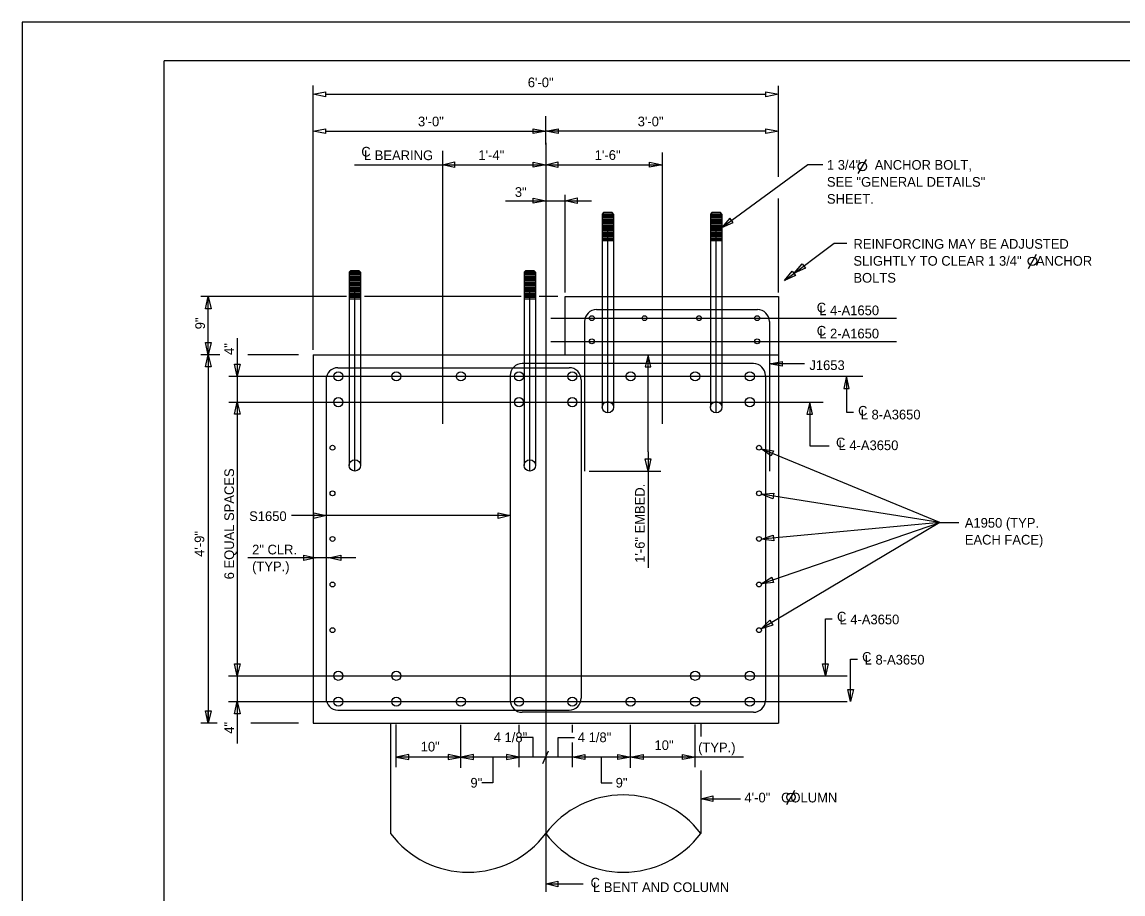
# Model space of a CAD drawing. Extents: x -133.1 to -97, y -1.7 to 20.3.
# Drawn here: x -133.14 to -118.94, y 9.06 to 20.31 of the extents above; entities that cross this region are included whole.
import ezdxf

# ---------------------------------------------------------------- set-up
doc = ezdxf.new("R2010")
doc.units = 0
for name, color, linetype in [('BR_AUTO DIMENSION', 7, 'Continuous'), ('BR_BORDER LINES', 7, 'Continuous'), ('BR_CENTER LINES', 7, 'Continuous'), ('BR_CONCRETE', 7, 'Continuous'), ('BR_REBAR', 7, 'Continuous'), ('BR_STRUCTURAL STEEL', 7, 'Continuous'), ('BR_TEXT', 7, 'Continuous'), ('Level 31', 7, 'Continuous')]:
    doc.layers.add(name, color=color, linetype=linetype)

msp = doc.modelspace()

# ---------------------------------------------------------------- linework, layer by layer
at = {"layer": 'BR_AUTO DIMENSION'}
for p, q in [((-129.388, 16.08), (-129.388, 19.492)), ((-123.388, 18.314), (-123.388, 19.485)), ((-129.221, 19.378), (-123.555, 19.378)), ((-126.388, 18.729), (-126.388, 19.097)), ((-129.221, 18.902), (-126.388, 18.902)), ((-123.555, 18.902), (-126.388, 18.902)), ((-128.854, 18.469), (-124.888, 18.469)), ((-126.388, 18.083), (-126.388, 17.91)), ((-126.138, 16.822), (-126.138, 18.081)), ((-123.388, 16.82), (-123.388, 18.032)), ((-126.908, 18.005), (-125.796, 18.005)), ((-128.958, 16.768), (-130.837, 16.768)), ((-130.74, 16.018), (-130.74, 16.768)), ((-126.703, 16.768), (-128.724, 16.768)), ((-126.231, 16.768), (-126.471, 16.768)), ((-130.365, 16.232), (-130.365, 11.006)), ((-130.589, 16.018), (-130.837, 16.018)), ((-130.74, 16.018), (-130.74, 11.268)), ((-129.575, 16.018), (-130.228, 16.018)), ((-125.068, 14.768), (-125.068, 16.018)), ((-123.051, 15.901), (-123.504, 15.901)), ((-122.983, 15.407), (-122.983, 14.845)), ((-125.068, 14.768), (-125.068, 13.272)), ((-121.307, 13.856), (-123.609, 14.806)), ((-122.983, 14.845), (-122.732, 14.845)), ((-125.826, 14.518), (-124.905, 14.518)), ((-121.307, 13.856), (-123.608, 14.222)), ((-126.846, 13.943), (-129.668, 13.943)), ((-121.307, 13.856), (-123.612, 12.483)), ((-121.307, 13.856), (-123.607, 13.64)), ((-128.835, 13.399), (-130.227, 13.399)), ((-130.626, 11.268), (-130.837, 11.268)), ((-129.575, 11.268), (-130.192, 11.268)), ((-128.315, 10.698), (-128.315, 11.249)), ((-127.482, 10.692), (-127.482, 11.244)), ((-126.732, 11.146), (-126.732, 11.246)), ((-126.044, 11.146), (-126.044, 11.246)), ((-125.294, 10.692), (-125.294, 11.244)), ((-124.461, 10.698), (-124.461, 11.249)), ((-126.55, 11.084), (-126.757, 11.084)), ((-126.55, 10.83), (-126.55, 11.084)), ((-126.226, 10.83), (-126.226, 11.084)), ((-126.226, 11.084), (-126.019, 11.084)), ((-126.732, 10.698), (-126.732, 11.016)), ((-126.044, 10.698), (-126.044, 11.016)), ((-123.839, 10.83), (-128.315, 10.83)), ((-127.068, 10.83), (-127.068, 10.498)), ((-126.425, 10.747), (-126.351, 10.912)), ((-125.675, 10.83), (-125.675, 10.498)), ((-127.068, 10.498), (-127.212, 10.498)), ((-125.675, 10.498), (-125.531, 10.498)), ((-124.388, 10.293), (-123.876, 10.293)), ((-126.388, 9.194), (-125.905, 9.194))]:
    msp.add_line(p, q, dxfattribs=at)
for points in [[(-129.226, 19.346), (-129.388, 19.378), (-129.226, 19.409)], [(-123.551, 19.409), (-123.388, 19.378), (-123.551, 19.346)], [(-129.226, 18.871), (-129.388, 18.902), (-129.226, 18.933)], [(-126.551, 18.933), (-126.388, 18.902), (-126.551, 18.871)], [(-126.226, 18.871), (-126.388, 18.902), (-126.226, 18.933)], [(-123.551, 18.933), (-123.388, 18.902), (-123.551, 18.871)], [(-127.565, 18.433), (-127.721, 18.469), (-127.565, 18.505)], [(-126.551, 18.501), (-126.388, 18.469), (-126.551, 18.438)], [(-126.232, 18.433), (-126.388, 18.469), (-126.232, 18.505)], [(-125.051, 18.501), (-124.888, 18.469), (-125.051, 18.438)], [(-126.551, 18.036), (-126.388, 18.005), (-126.551, 17.974)], [(-125.982, 17.969), (-126.138, 18.005), (-125.982, 18.041)], [(-124.012, 17.78), (-124.117, 17.659), (-123.97, 17.722)], [(-123.04, 17.134), (-123.186, 17.069), (-123.083, 17.191)], [(-123.165, 17.04), (-123.311, 16.976), (-123.208, 17.098)], [(-130.776, 16.612), (-130.74, 16.768), (-130.704, 16.612)], [(-130.704, 16.174), (-130.74, 16.018), (-130.776, 16.174)], [(-130.776, 15.862), (-130.74, 16.018), (-130.704, 15.862)], [(-125.032, 15.862), (-125.068, 16.018), (-125.104, 15.862)], [(-123.341, 15.87), (-123.504, 15.901), (-123.341, 15.933)], [(-130.329, 15.896), (-130.365, 15.74), (-130.401, 15.896)], [(-122.473, 15.584), (-122.509, 15.74), (-122.545, 15.584)], [(-130.401, 15.251), (-130.365, 15.407), (-130.329, 15.251)], [(-122.947, 15.251), (-122.983, 15.407), (-123.019, 15.251)], [(-123.479, 14.714), (-123.609, 14.806), (-123.451, 14.78)], [(-125.032, 14.674), (-125.068, 14.518), (-125.104, 14.674)], [(-123.46, 14.161), (-123.608, 14.222), (-123.448, 14.233)], [(-129.377, 13.979), (-129.221, 13.943), (-129.377, 13.907)], [(-127.002, 13.979), (-126.846, 13.943), (-127.002, 13.907)], [(-123.448, 13.619), (-123.607, 13.64), (-123.455, 13.691)], [(-129.509, 13.435), (-129.353, 13.399), (-129.509, 13.363)], [(-129.03, 13.363), (-129.186, 13.399), (-129.03, 13.435)], [(-123.449, 13.082), (-123.609, 13.065), (-123.473, 13.15)], [(-123.459, 12.532), (-123.612, 12.483), (-123.496, 12.594)], [(-130.329, 12.034), (-130.365, 11.878), (-130.401, 12.034)], [(-122.745, 12.034), (-122.781, 11.878), (-122.817, 12.034)], [(-122.421, 11.701), (-122.457, 11.545), (-122.493, 11.701)], [(-130.401, 11.389), (-130.365, 11.545), (-130.329, 11.389)], [(-130.704, 11.424), (-130.74, 11.268), (-130.776, 11.424)], [(-128.153, 10.861), (-128.315, 10.83), (-128.153, 10.799)], [(-127.644, 10.799), (-127.482, 10.83), (-127.644, 10.861)], [(-127.319, 10.861), (-127.482, 10.83), (-127.319, 10.799)], [(-126.894, 10.799), (-126.732, 10.83), (-126.894, 10.861)], [(-125.882, 10.799), (-126.044, 10.83), (-125.882, 10.861)], [(-125.457, 10.861), (-125.294, 10.83), (-125.457, 10.799)], [(-125.132, 10.799), (-125.294, 10.83), (-125.132, 10.861)], [(-124.623, 10.861), (-124.461, 10.83), (-124.623, 10.799)], [(-124.232, 10.257), (-124.388, 10.293), (-124.232, 10.329)], [(-126.232, 9.158), (-126.388, 9.194), (-126.232, 9.23)]]:
    msp.add_lwpolyline(points, close=True, dxfattribs=at)
for points in [[(-124.117, 17.659), (-123.008, 18.471), (-122.816, 18.471)], [(-123.311, 16.976), (-122.67, 17.455), (-122.505, 17.455)], [(-122.509, 15.74), (-122.509, 15.277), (-122.421, 15.277)], [(-123.609, 13.065), (-121.307, 13.856), (-121.06, 13.856)], [(-122.781, 11.878), (-122.781, 12.611), (-122.694, 12.611)], [(-122.457, 11.545), (-122.457, 12.091), (-122.369, 12.091)]]:
    msp.add_lwpolyline(points, dxfattribs=at)
at = {"layer": 'BR_BORDER LINES'}
for p in [(-97.642, 19.809), (-131.308, -1.191)]:
    msp.add_line(p, (-131.308, 19.809), dxfattribs=at)
at = {"layer": 'BR_CENTER LINES'}
for p, q in [((-126.388, 18.751), (-126.388, 9.09)), ((-127.721, 18.647), (-127.721, 15.128)), ((-124.888, 18.628), (-124.888, 15.128)), ((-125.586, 15.268), (-125.586, 17.64)), ((-124.19, 15.268), (-124.19, 17.64)), ((-128.849, 14.518), (-128.849, 16.89)), ((-126.593, 14.518), (-126.593, 16.89)), ((-126.323, 16.49), (-121.865, 16.49)), ((-126.323, 16.191), (-121.865, 16.191)), ((-130.476, 15.74), (-122.3, 15.74)), ((-130.476, 15.407), (-122.812, 15.407)), ((-130.477, 11.878), (-122.502, 11.878)), ((-130.477, 11.545), (-122.502, 11.545))]:
    msp.add_line(p, q, dxfattribs=at)
at = {"layer": 'BR_CONCRETE'}
for p, q in [((-126.138, 16.018), (-126.138, 16.768)), ((-126.138, 16.768), (-123.388, 16.768)), ((-123.388, 16.768), (-123.388, 11.268)), ((-129.388, 16.018), (-129.388, 11.268)), ((-129.388, 16.018), (-123.388, 16.018)), ((-129.388, 11.268), (-123.388, 11.268)), ((-128.388, 11.268), (-128.388, 9.843)), ((-124.388, 11.268), (-124.388, 11.095)), ((-124.388, 10.656), (-124.388, 9.843))]:
    msp.add_line(p, q, dxfattribs=at)
for centre, start, end in [((-125.388, 9.09), 37.0023, 142.9977), ((-127.388, 10.597), 217.0023, 322.9977), ((-125.388, 10.597), 217.0023, 322.9977)]:
    msp.add_arc(centre, 1.252, start, end, dxfattribs=at)
at = {"layer": 'BR_REBAR'}
for p, q in [((-125.732, 16.601), (-123.658, 16.601)), ((-125.886, 16.447), (-125.886, 14.518)), ((-123.504, 16.447), (-123.504, 14.518)), ((-123.709, 15.905), (-126.69, 15.905)), ((-129.067, 15.851), (-126.086, 15.851)), ((-129.221, 15.697), (-129.221, 11.588)), ((-126.846, 15.749), (-126.846, 11.563)), ((-125.93, 15.695), (-125.93, 11.591)), ((-123.555, 15.747), (-123.555, 11.561)), ((-129.067, 11.434), (-126.086, 11.434)), ((-123.709, 11.407), (-126.69, 11.407))]:
    msp.add_line(p, q, dxfattribs=at)
for centre, radius in [((-125.793, 16.49), 0.0313), ((-125.113, 16.49), 0.0313), ((-124.411, 16.49), 0.0313), ((-123.662, 16.49), 0.0313), ((-125.793, 16.191), 0.0313), ((-123.662, 16.191), 0.0313), ((-129.063, 15.74), 0.0588), ((-128.315, 15.74), 0.0588), ((-127.482, 15.74), 0.0588), ((-126.732, 15.74), 0.0588), ((-126.044, 15.74), 0.0588), ((-125.294, 15.74), 0.0588), ((-124.461, 15.74), 0.0588), ((-123.756, 15.74), 0.0588), ((-129.063, 15.407), 0.0588), ((-126.732, 15.407), 0.0588), ((-126.044, 15.407), 0.0588), ((-123.756, 15.407), 0.0588), ((-129.138, 14.819), 0.0313), ((-123.638, 14.819), 0.0313), ((-129.138, 14.231), 0.0313), ((-123.638, 14.231), 0.0313), ((-129.138, 13.643), 0.0313), ((-123.638, 13.643), 0.0313), ((-129.138, 13.055), 0.0313), ((-123.638, 13.055), 0.0313), ((-129.138, 12.467), 0.0313), ((-123.638, 12.467), 0.0313), ((-129.063, 11.878), 0.0588), ((-128.315, 11.878), 0.0588), ((-124.461, 11.878), 0.0588), ((-123.756, 11.878), 0.0588), ((-129.063, 11.545), 0.0588), ((-128.315, 11.545), 0.0588), ((-127.482, 11.545), 0.0588), ((-126.732, 11.545), 0.0588), ((-126.044, 11.545), 0.0588), ((-125.294, 11.545), 0.0588), ((-124.461, 11.545), 0.0588), ((-123.756, 11.545), 0.0588)]:
    msp.add_circle(centre, radius, dxfattribs=at)
for centre, start, end in [((-125.73, 16.445), 91.025, 178.975), ((-123.66, 16.445), 1.025, 88.975), ((-126.69, 15.749), 90, 180), ((-123.711, 15.749), 1.025, 88.975), ((-129.065, 15.695), 91.025, 178.975), ((-126.086, 15.695), 0, 90), ((-129.065, 11.591), 181.025, 268.975), ((-126.69, 11.563), 180, 270), ((-126.086, 11.591), 270, 0), ((-123.711, 11.563), 271.025, 358.975)]:
    msp.add_arc(centre, 0.156, start, end, dxfattribs=at)
at = {"layer": 'BR_STRUCTURAL STEEL'}
for p, q in [((-125.641, 17.851), (-125.659, 17.833)), ((-125.513, 17.833), (-125.659, 17.833)), ((-125.659, 17.833), (-125.659, 16.768)), ((-125.513, 17.815), (-125.659, 17.815)), ((-125.513, 17.797), (-125.659, 17.797)), ((-125.513, 17.778), (-125.659, 17.778)), ((-125.513, 17.76), (-125.659, 17.76)), ((-125.532, 17.851), (-125.641, 17.851)), ((-125.513, 17.833), (-125.532, 17.851)), ((-125.513, 17.833), (-125.513, 16.768)), ((-124.244, 17.851), (-124.263, 17.833)), ((-124.117, 17.833), (-124.263, 17.833)), ((-124.263, 17.833), (-124.263, 16.768)), ((-124.117, 17.815), (-124.263, 17.815)), ((-124.117, 17.797), (-124.263, 17.797)), ((-124.117, 17.778), (-124.263, 17.778)), ((-124.117, 17.76), (-124.263, 17.76)), ((-124.135, 17.851), (-124.244, 17.851)), ((-124.117, 17.833), (-124.135, 17.851)), ((-124.117, 17.833), (-124.117, 16.768)), ((-125.513, 17.742), (-125.659, 17.742)), ((-125.513, 17.724), (-125.659, 17.724)), ((-125.513, 17.705), (-125.659, 17.705)), ((-125.513, 17.687), (-125.659, 17.687)), ((-125.513, 17.669), (-125.659, 17.669)), ((-125.513, 17.651), (-125.659, 17.651)), ((-125.513, 17.632), (-125.659, 17.632)), ((-125.513, 17.614), (-125.659, 17.614)), ((-124.117, 17.742), (-124.263, 17.742)), ((-124.117, 17.724), (-124.263, 17.724)), ((-124.117, 17.705), (-124.263, 17.705)), ((-124.117, 17.687), (-124.263, 17.687)), ((-124.117, 17.669), (-124.263, 17.669)), ((-124.117, 17.651), (-124.263, 17.651)), ((-124.117, 17.632), (-124.263, 17.632)), ((-124.117, 17.614), (-124.263, 17.614)), ((-125.513, 17.596), (-125.659, 17.596)), ((-125.513, 17.578), (-125.659, 17.578)), ((-125.513, 17.56), (-125.659, 17.56)), ((-125.513, 17.541), (-125.659, 17.541)), ((-125.513, 17.523), (-125.659, 17.523)), ((-125.513, 17.505), (-125.659, 17.505)), ((-125.513, 17.487), (-125.659, 17.487)), ((-124.117, 17.596), (-124.263, 17.596)), ((-124.117, 17.578), (-124.263, 17.578)), ((-124.117, 17.56), (-124.263, 17.56)), ((-124.117, 17.541), (-124.263, 17.541)), ((-124.117, 17.523), (-124.263, 17.523)), ((-124.117, 17.505), (-124.263, 17.505)), ((-124.117, 17.487), (-124.263, 17.487)), ((-128.904, 17.101), (-128.922, 17.083)), ((-128.776, 17.083), (-128.922, 17.083)), ((-128.922, 17.083), (-128.922, 16.018)), ((-128.776, 17.065), (-128.922, 17.065)), ((-128.776, 17.047), (-128.922, 17.047)), ((-128.795, 17.101), (-128.904, 17.101)), ((-128.776, 17.083), (-128.795, 17.101)), ((-128.776, 17.083), (-128.776, 16.018)), ((-126.648, 17.101), (-126.666, 17.083)), ((-126.52, 17.083), (-126.666, 17.083)), ((-126.666, 17.083), (-126.666, 16.018)), ((-126.52, 17.065), (-126.666, 17.065)), ((-126.52, 17.047), (-126.666, 17.047)), ((-126.539, 17.101), (-126.648, 17.101)), ((-126.52, 17.083), (-126.539, 17.101)), ((-126.52, 17.083), (-126.52, 16.018)), ((-128.776, 17.028), (-128.922, 17.028)), ((-128.776, 17.01), (-128.922, 17.01)), ((-128.776, 16.992), (-128.922, 16.992)), ((-128.776, 16.974), (-128.922, 16.974)), ((-128.776, 16.955), (-128.922, 16.955)), ((-128.776, 16.937), (-128.922, 16.937)), ((-128.776, 16.919), (-128.922, 16.919)), ((-128.776, 16.901), (-128.922, 16.901)), ((-126.52, 17.028), (-126.666, 17.028)), ((-126.52, 17.01), (-126.666, 17.01)), ((-126.52, 16.992), (-126.666, 16.992)), ((-126.52, 16.974), (-126.666, 16.974)), ((-126.52, 16.955), (-126.666, 16.955)), ((-126.52, 16.937), (-126.666, 16.937)), ((-126.52, 16.919), (-126.666, 16.919)), ((-126.52, 16.901), (-126.666, 16.901)), ((-128.776, 16.882), (-128.922, 16.882)), ((-128.776, 16.864), (-128.922, 16.864)), ((-128.776, 16.846), (-128.922, 16.846)), ((-128.776, 16.828), (-128.922, 16.828)), ((-128.776, 16.81), (-128.922, 16.81)), ((-128.776, 16.791), (-128.922, 16.791)), ((-128.776, 16.773), (-128.922, 16.773)), ((-128.776, 16.755), (-128.922, 16.755)), ((-126.52, 16.882), (-126.666, 16.882)), ((-126.52, 16.864), (-126.666, 16.864)), ((-126.52, 16.846), (-126.666, 16.846)), ((-126.52, 16.828), (-126.666, 16.828)), ((-126.52, 16.81), (-126.666, 16.81)), ((-126.52, 16.791), (-126.666, 16.791)), ((-126.52, 16.773), (-126.666, 16.773)), ((-126.52, 16.755), (-126.666, 16.755)), ((-125.659, 16.768), (-125.659, 15.341)), ((-125.513, 16.768), (-125.513, 15.341)), ((-124.263, 16.768), (-124.263, 15.341)), ((-124.117, 16.768), (-124.117, 15.341)), ((-128.776, 16.737), (-128.922, 16.737)), ((-126.52, 16.737), (-126.666, 16.737)), ((-128.922, 16.018), (-128.922, 14.591)), ((-128.776, 16.018), (-128.776, 14.591)), ((-126.666, 16.018), (-126.666, 14.591)), ((-126.52, 16.018), (-126.521, 14.591))]:
    msp.add_line(p, q, dxfattribs=at)
for centre in [(-125.586, 15.341), (-124.19, 15.341), (-128.849, 14.591), (-126.593, 14.591)]:
    msp.add_circle(centre, 0.0729, dxfattribs=at)
at = {"layer": 'BR_TEXT'}
for p, q in [((-122.357, 18.356), (-122.252, 18.537)), ((-120.164, 17.132), (-120.059, 17.314)), ((-130.74, 11.268), (-130.74, 11.415)), ((-123.279, 10.22), (-123.174, 10.402))]:
    msp.add_line(p, q, dxfattribs=at)
for centre in [(-122.305, 18.447), (-120.111, 17.223), (-123.226, 10.311)]:
    msp.add_circle(centre, 0.055, dxfattribs=at)
at = {"layer": 'Level 31'}
msp.add_lwpolyline([(-133.141, -1.691), (-97.141, -1.691), (-97.141, 20.309), (-133.141, 20.309)], close=True, dxfattribs=at)

# ---------------------------------------------------------------- texts
at = {"layer": 'BR_AUTO DIMENSION'}
for s, p in [('6\'-0"', (-126.619, 19.468)), ('3\'-0"', (-128.035, 18.964)), ('3\'-0"', (-125.202, 18.964))]:
    msp.add_text(s, height=0.125, dxfattribs=at).set_placement(p)
at = {"layer": 'BR_TEXT'}
for s, rotation, p in [('C', 360, (-128.766, 18.574)), ('L BEARING', 360, (-128.732, 18.528)), ('1\'-4"', 360, (-127.256, 18.531)), ('1\'-6"', 360, (-125.756, 18.531)), ('1 3/4"    ANCHOR BOLT, ', 360, (-122.762, 18.404)), ('3"', 360, (-126.786, 18.054)), ('SEE "GENERAL DETAILS"', 360, (-122.762, 18.185)), ('SHEET.', 360, (-122.762, 17.966)), ('REINFORCING MAY BE ADJUSTED', 360, (-122.42, 17.385)), ('SLIGHTLY TO CLEAR 1 3/4"    ANCHOR', 360, (-122.42, 17.166)), ('BOLTS', 360, (-122.42, 16.948)), ('C', 360, (-122.893, 16.564)), ('L 4-A1650', 360, (-122.861, 16.528)), ('9"', 90, (-130.782, 16.346)), ('C', 360, (-122.893, 16.265)), ('L 2-A1650', 360, (-122.861, 16.229)), ('4"', 90, (-130.407, 16.015)), ('J1653', 360, (-122.988, 15.821)), ('C', 360, (-122.36, 15.233)), ('L 8-A3650', 360, (-122.326, 15.184)), ('C', 360, (-122.645, 14.824)), ('L 4-A3650', 360, (-122.612, 14.788)), ('6 EQUAL SPACES', 90, (-130.407, 13.122)), ('1\'-6" EMBED.', 90, (-125.111, 13.335)), ('S1650', 360, (-130.212, 13.874)), ('A1950 (TYP.', 360, (-120.984, 13.788)), ('4\'-9"', 90, (-130.791, 13.412)), ('EACH FACE)', 360, (-120.984, 13.57)), ('2" CLR.', 360, (-130.174, 13.443)), ('(TYP.)', 360, (-130.174, 13.225)), ('C', 360, (-122.632, 12.578)), ('L 4-A3650', 360, (-122.6, 12.542)), ('C', 360, (-122.308, 12.059)), ('L 8-A3650', 360, (-122.275, 12.023)), ('4"', 90, (-130.407, 11.131)), ('10"', 360, (-128, 10.902)), ('10"', 360, (-124.985, 10.921)), ('(TYP.)', 360, (-124.423, 10.891)), ('9"', 360, (-127.359, 10.436)), ('9"', 360, (-125.486, 10.436)), ('4\'-0"   COLUMN', 360, (-123.825, 10.245)), ('C', 360, (-125.81, 9.148)), ('L BENT AND COLUMN', 360, (-125.778, 9.089))]:
    msp.add_text(s, height=0.125, rotation=rotation, dxfattribs=at).set_placement(p)
for p in [(-127.058, 11.022), (-125.974, 11.022)]:
    msp.add_text('4 1/8"', height=0.125, dxfattribs=at).set_placement(p)

doc.saveas('drawing.dxf')
